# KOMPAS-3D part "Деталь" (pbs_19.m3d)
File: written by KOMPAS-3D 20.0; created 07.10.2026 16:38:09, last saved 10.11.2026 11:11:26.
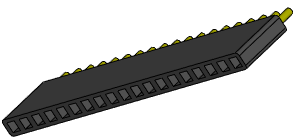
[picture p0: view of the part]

Document properties: Полное имя файла: D:\myProjects\Progect_esp32\box_compas\разъемы\pbs_19.m3d

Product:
- Part/product: Деталь
    Масса: 0.00577391
  - Body: Тело 1
      Масса: 0.00578824

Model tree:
1. Эскиз:1
2. Элемент выдавливания:1
     Расстояние 1 = 8.5
3. Эскиз:2  (with: Элемент выдавливания:1)
4. Элемент выдавливания:2
     Расстояние 1 = 3
5. Массив по сетке:2  (with: Элемент выдавливания:2, Эскиз:2)  (19 pattern instances)
     Шаг 1 = 2.54; Угол раствора = 90
6. Эскиз:3  (with: Элемент выдавливания:1)
7. Элемент выдавливания:3
     Расстояние 2 = 8
8. Массив по сетке:3  (with: Элемент выдавливания:3, Эскиз:3)  (19 pattern instances)
     Шаг 1 = 2.54; Угол раствора = 90; Геометрический массив = 128
9. Скругление:1  (with: Элемент выдавливания:1)
     Радиус = 0.5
